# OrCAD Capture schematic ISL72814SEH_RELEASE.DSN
size A; title: 02_IVCC; rev: 0; note: ISL72814SEH 02_IVCC
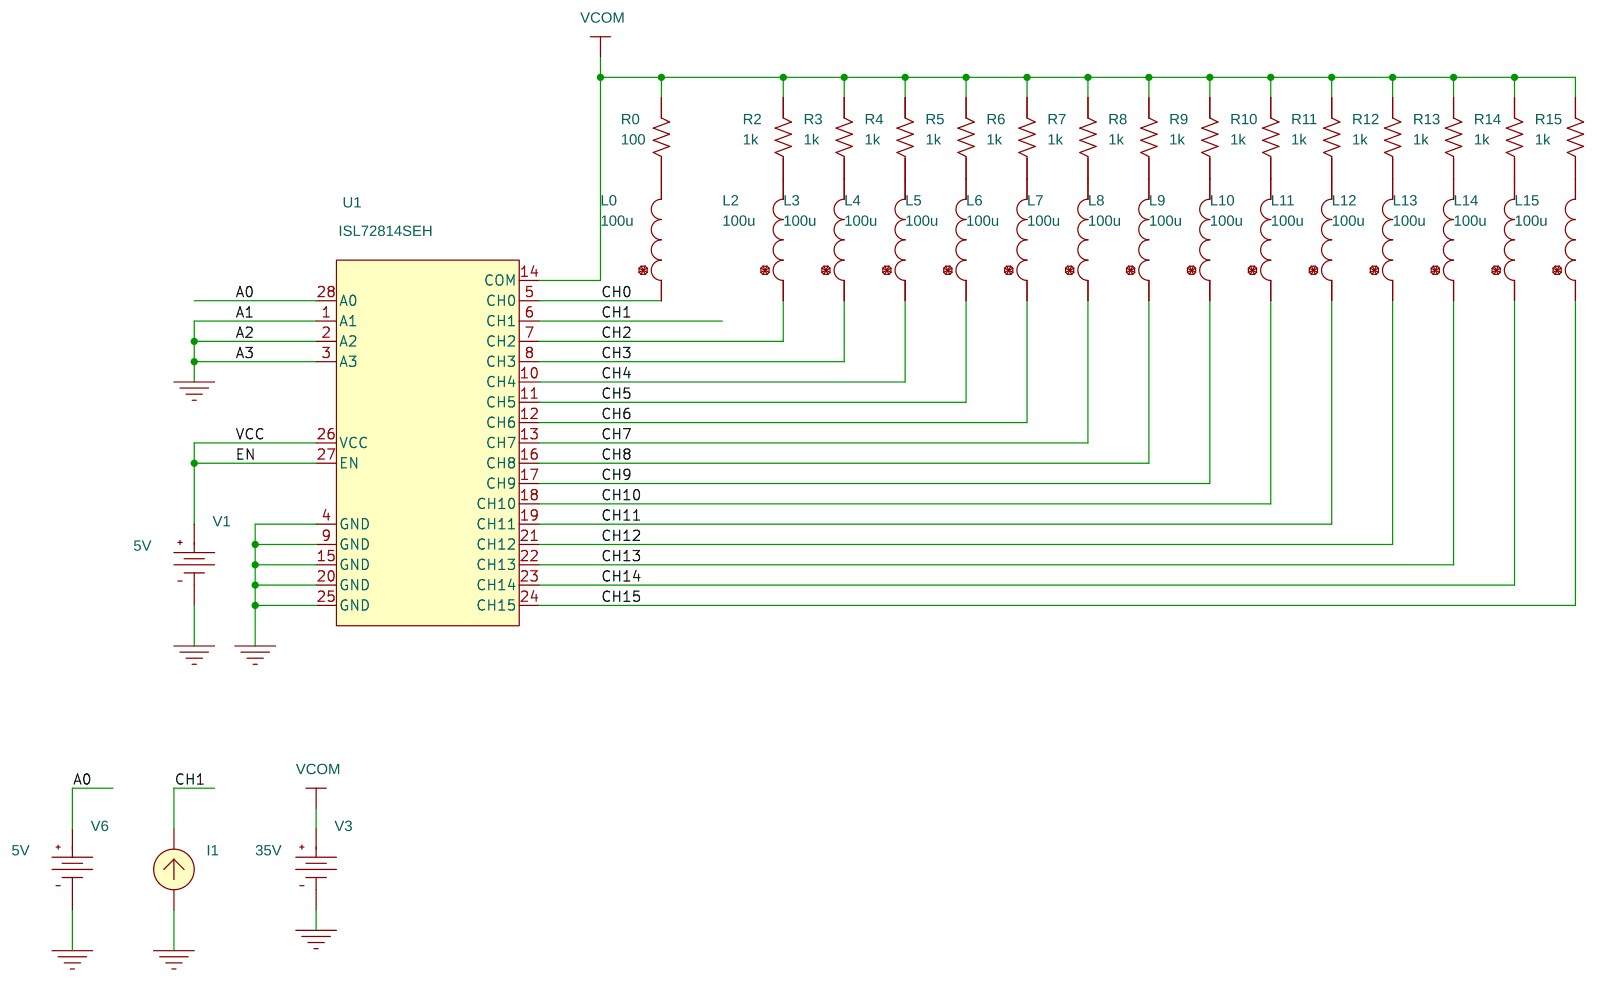
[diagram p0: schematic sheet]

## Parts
I1  IDC
L0  100u  [DISC350x175LS200x100034]
L2  100u  [DISC350x175LS200x100034]
L3  100u  [DISC350x175LS200x100034]
L4  100u  [DISC350x175LS200x100034]
L5  100u  [DISC350x175LS200x100034]
L6  100u  [DISC350x175LS200x100034]
L7  100u  [DISC350x175LS200x100034]
L8  100u  [DISC350x175LS200x100034]
L9  100u  [DISC350x175LS200x100034]
L10  100u  [DISC350x175LS200x100034]
L11  100u  [DISC350x175LS200x100034]
L12  100u  [DISC350x175LS200x100034]
L13  100u  [DISC350x175LS200x100034]
L14  100u  [DISC350x175LS200x100034]
L15  100u  [DISC350x175LS200x100034]
R0  100  [AXRC05]
R2  1k  [AXRC05]
R3  1k  [AXRC05]
R4  1k  [AXRC05]
R5  1k  [AXRC05]
R6  1k  [AXRC05]
R7  1k  [AXRC05]
R8  1k  [AXRC05]
R9  1k  [AXRC05]
R10  1k  [AXRC05]
R11  1k  [AXRC05]
R12  1k  [AXRC05]
R13  1k  [AXRC05]
R14  1k  [AXRC05]
R15  1k  [AXRC05]
U1  ISL72814SEH
V1  VDC
V3  VDC
V6  VDC

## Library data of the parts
I1 = IDC
L0 L2-L15 = L
R0 R2-R15 = R
U1 = ISL72814SEH
V1 V6 = VDC: DC: 5V
V3 = VDC: DC: 35V

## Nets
0: I1.1(+) U1.1(A1) U1.2(A2) U1.3(A3) U1.4(GND) U1.9(GND) U1.15(GND) U1.20(GND) U1.25(GND) V1.1(-) V3.1(-) V6.1(-)
A0: U1.28(A0) V6.0(+)
CH0: L0.1 U1.5(CH0)
CH1: I1.2(-) U1.6(CH1)
CH2: L2.1 U1.7(CH2)
CH3: L3.1 U1.8(CH3)
CH4: L4.1 U1.10(CH4)
CH5: L5.1 U1.11(CH5)
CH6: L6.1 U1.12(CH6)
CH7: L7.1 U1.13(CH7)
CH8: L8.1 U1.16(CH8)
CH9: L9.1 U1.17(CH9)
CH10: L10.1 U1.18(CH10)
CH11: L11.1 U1.19(CH11)
CH12: L12.1 U1.21(CH12)
CH13: L13.1 U1.22(CH13)
CH14: L14.1 U1.23(CH14)
CH15: L15.1 U1.24(CH15)
EN: U1.26(VCC) U1.27(EN) V1.0(+)
VCOM: R0.2 R2.2 R3.2 R4.2 R5.2 R6.2 R7.2 R8.2 R9.2 R10.2 R11.2 R12.2 R13.2 R14.2 R15.2 U1.14(COM) V3.0(+)
N21834: L3.2 R3.1
N21835: L13.2 R13.1
N21836: L8.2 R8.1
N21837: L14.2 R14.1
N21838: L7.2 R7.1
N21839: L0.2 R0.1
N21840: L15.2 R15.1
N21841: L11.2 R11.1
N21842: L12.2 R12.1
N21843: L6.2 R6.1
N21844: L10.2 R10.1
N21845: L2.2 R2.1
N21846: L5.2 R5.1
N21847: L9.2 R9.1
N21848: L4.2 R4.1
